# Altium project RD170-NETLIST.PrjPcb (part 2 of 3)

## Sheet 2.SchDoc
size 420 x 297 mm
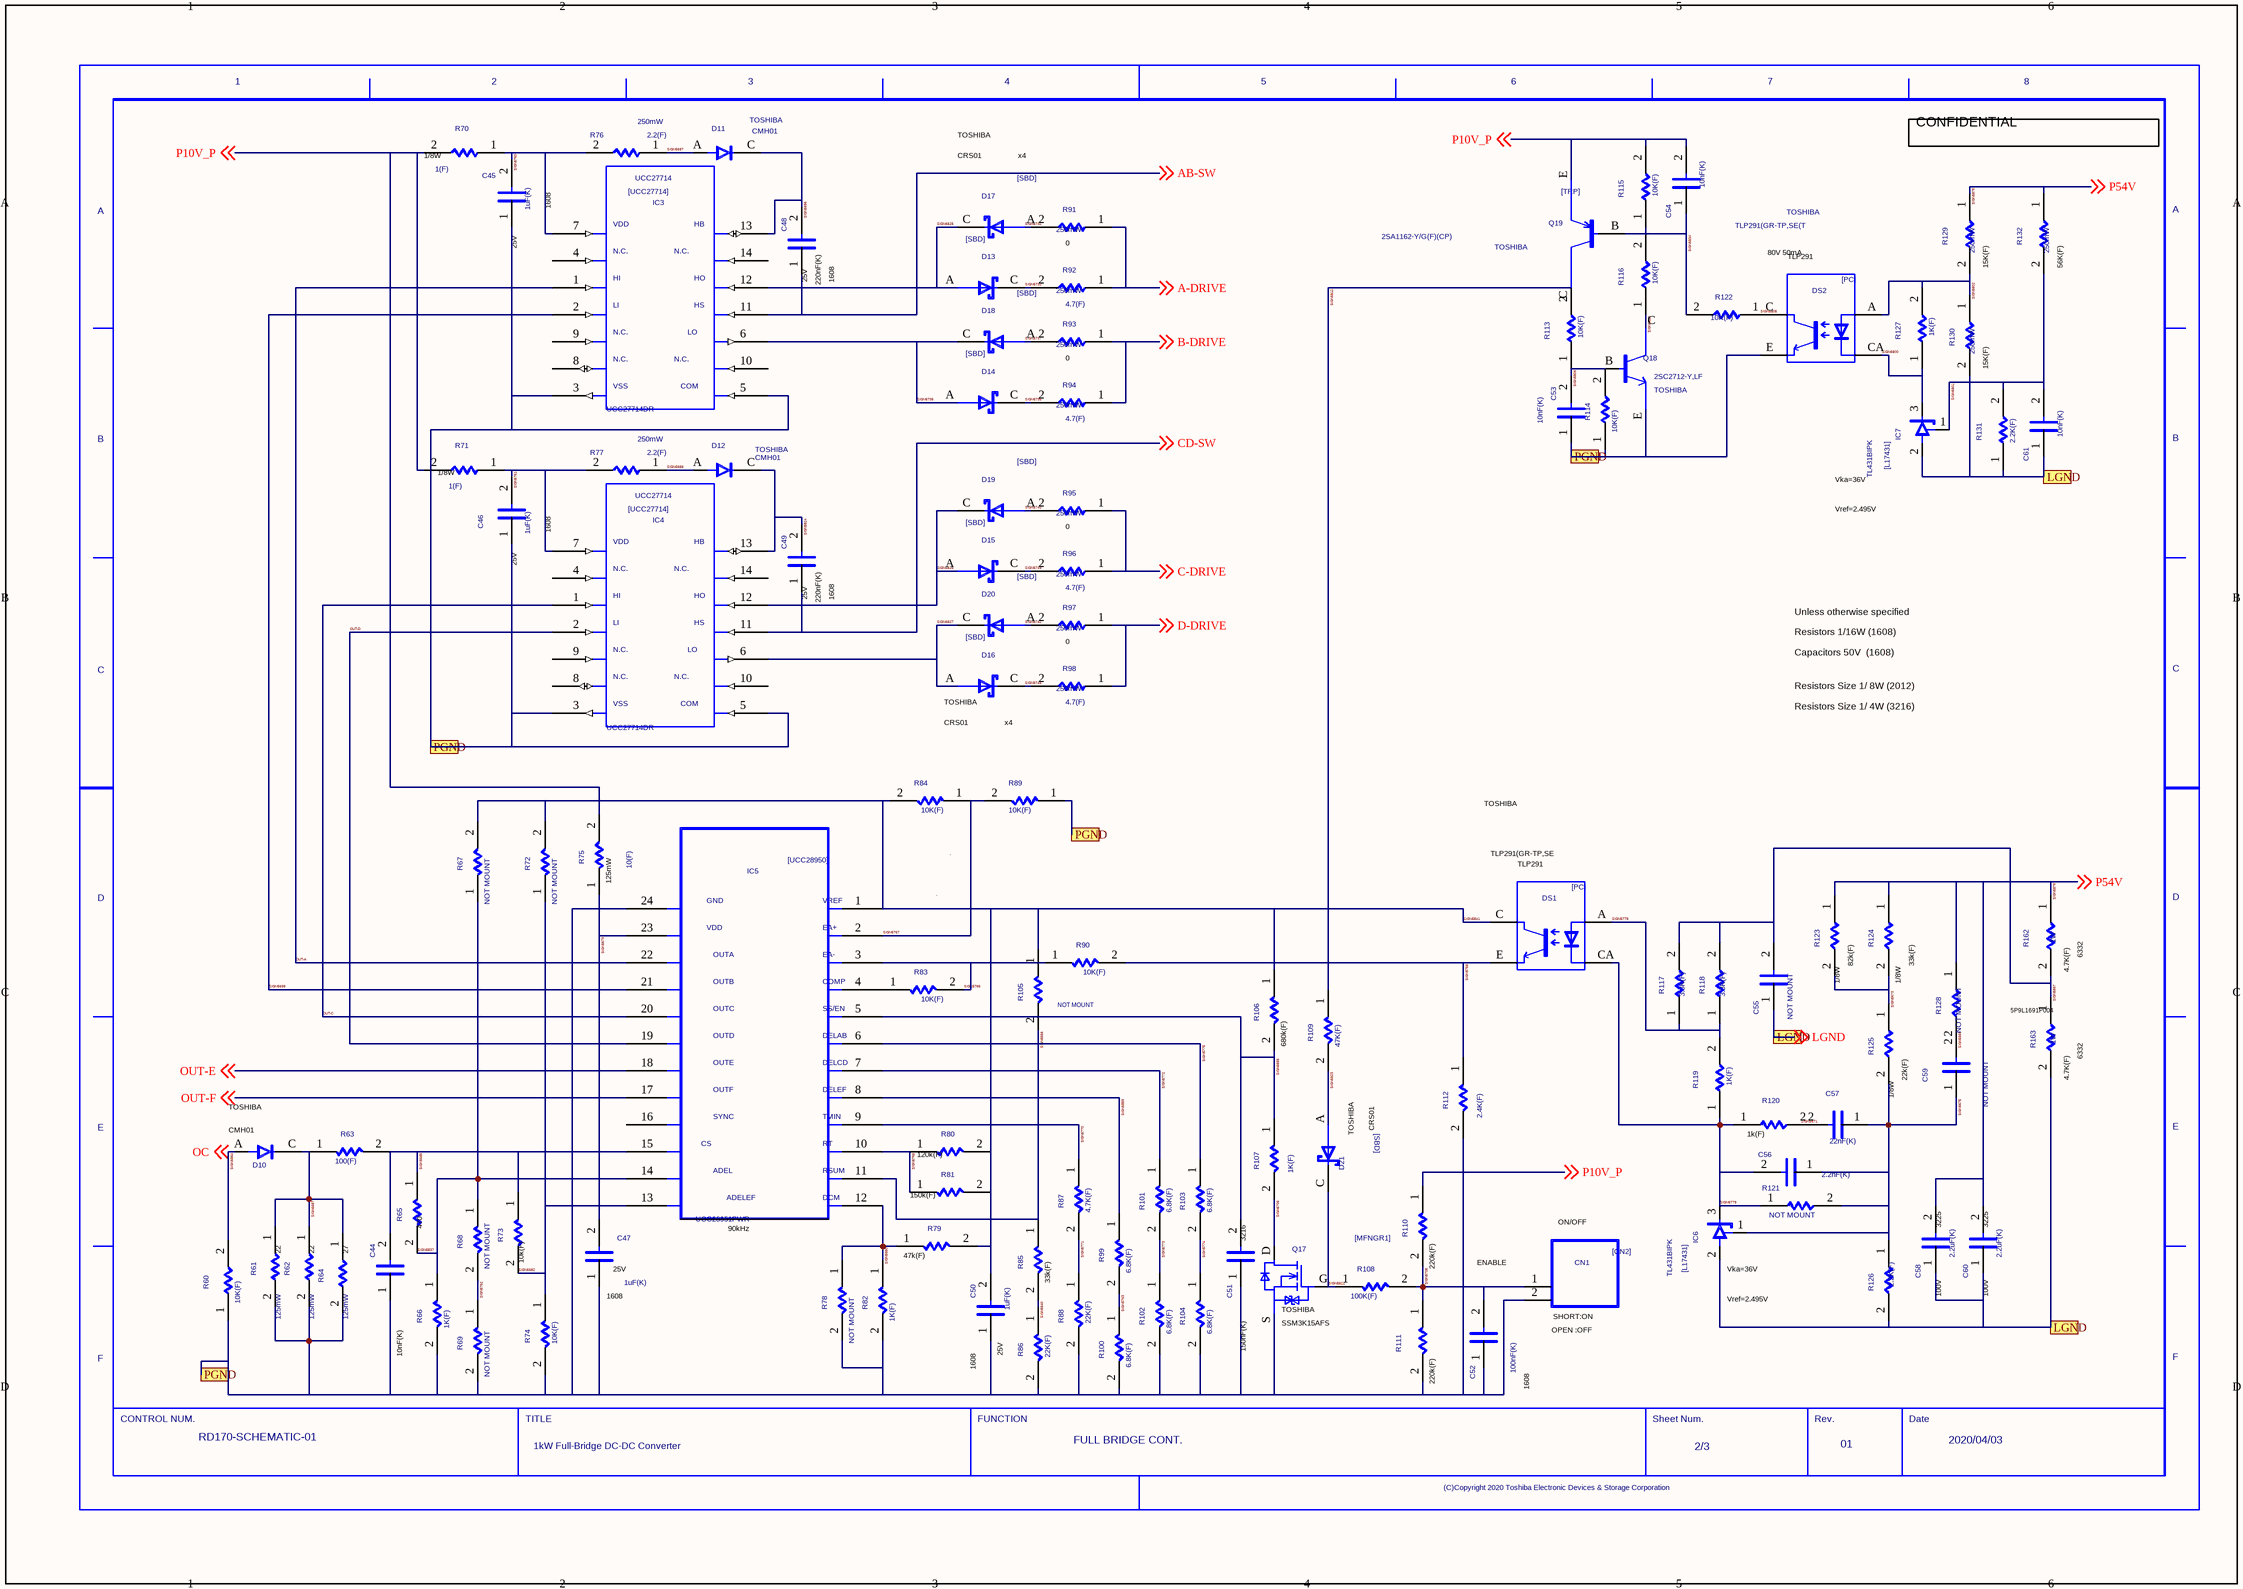
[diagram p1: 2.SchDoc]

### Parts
(Parts that share a designator on the sheet are numbered #1, #2 ... from top to bottom, then left to right.)
C44  C  (value not drawn)
C45  VAL1: 1uF(K)  (hidden comment: C)
C46  VAL1: 1uF(K)  (hidden comment: C)
C47  VAL1: 1uF(K)  (hidden comment: C)
C48  C  (value not drawn)
C49  C  (value not drawn)
C50  VAL1: 1uF(K)  (hidden comment: C)
C51  C  (value not drawn)
C52  VAL1: 100nF(K)  (hidden comment: C)
C53  VAL1: 10nF(K)  (hidden comment: C)
C54  VAL1: 10nF(K)  (hidden comment: C)
C55  NOTMOUNT: NOT MOUNT  (hidden comment: C)
C56  VAL1: 2.2nF(K)  (hidden comment: C)
C57  VAL1: 22nF(K)  (hidden comment: C)
C58  VAL1: 2.2uF(K)  (hidden comment: C)
C59  NOTMOUNT: NOT MOUNT  (hidden comment: C)
C60  VAL1: 2.2uF(K)  (hidden comment: C)
C61  VAL1: 10nF(K)  (hidden comment: C)
CN1  CN2  (value not drawn)
D10  D  (value not drawn)
D11  USERCOMPTEXT3: TOSHIBA  VAL3: CMH01  (hidden comment: D)
D12  USERCOMPTEXT3: TOSHIBA  VAL3: CMH01  (hidden comment: D)
D13  SBD  (value not drawn)
D14  SBD  (value not drawn)
D15  SBD  (value not drawn)
D16  SBD  (value not drawn)
D17  SBD  (value not drawn)
D18  SBD  (value not drawn)
D19  SBD  (value not drawn)
D20  SBD  (value not drawn)
D21  SBD  (value not drawn)
DS1  PC  (value not drawn)
DS2  USERCOMPTEXT3: TOSHIBA  VAL3: TLP291(GR-TP,SE(T  (hidden comment: PC)
IC3  VAL3: UCC27714DR  (hidden comment: UCC27714)
IC4  VAL3: UCC27714DR  (hidden comment: UCC27714)
IC5  VAL3: UCC28951PWR  (hidden comment: UCC28950)
IC6  VAL3: TL431BIPK  (hidden comment: L17431)
IC7  VAL3: TL431BIPK  (hidden comment: L17431)
Q17  MFNGR1  (value not drawn)
Q18  USERCOMPTEXT3: TOSHIBA  VAL3: 2SC2712-Y,LF  (hidden comment: TRN)
Q19  USERCOMPTEXT3: TOSHIBA  VAL3: 2SA1162-Y/G(F)(CP)  (hidden comment: TRP)
R60  VAL1: 10K(F)  (hidden comment: R)
R61  VAL2: 125mW  (hidden comment: R)
R62  VAL2: 125mW  (hidden comment: R)
R63  VAL1: 100(F)  (hidden comment: R)
R64  VAL2: 125mW  (hidden comment: R)
R65  R  (value not drawn)
R66  VAL1: 1K(F)  (hidden comment: R)
R67  NOTMOUNT: NOT MOUNT  (hidden comment: R)
R68  NOTMOUNT: NOT MOUNT  (hidden comment: R)
R69  NOTMOUNT: NOT MOUNT  (hidden comment: R)
R70  VAL1: 1(F)  (hidden comment: R)
R71  VAL1: 1(F)  (hidden comment: R)
R72  NOTMOUNT: NOT MOUNT  (hidden comment: R)
R73  R  (value not drawn)
R74  VAL1: 10K(F)  (hidden comment: R)
R75  VAL1: 10(F)  (hidden comment: R)
R76  VAL2: 250mW  VAL1: 2.2(F)  (hidden comment: R)
R77  VAL2: 250mW  VAL1: 2.2(F)  (hidden comment: R)
R78  NOTMOUNT: NOT MOUNT  (hidden comment: R)
R79  R  (value not drawn)
R80  R  (value not drawn)
R81  R  (value not drawn)
R82  VAL1: 1K(F)  (hidden comment: R)
R83  VAL1: 10K(F)  (hidden comment: R)
R84  VAL1: 10K(F)  (hidden comment: R)
R85  R  (value not drawn)
R86  VAL1: 22K(F)  (hidden comment: R)
R87  VAL1: 4.7K(F)  (hidden comment: R)
R88  VAL1: 22K(F)  (hidden comment: R)
R89  VAL1: 10K(F)  (hidden comment: R)
R90  VAL1: 10K(F)  (hidden comment: R)
R91  VAL2: 250mW  (hidden comment: R)
R92  VAL2: 250mW  VAL1: 4.7(F)  (hidden comment: R)
R93  VAL2: 250mW  (hidden comment: R)
R94  VAL2: 250mW  VAL1: 4.7(F)  (hidden comment: R)
R95  VAL2: 250mW  (hidden comment: R)
R96  VAL2: 250mW  VAL1: 4.7(F)  (hidden comment: R)
R97  VAL2: 250mW  (hidden comment: R)
R98  VAL2: 250mW  VAL1: 4.7(F)  (hidden comment: R)
R99  VAL1: 6.8K(F)  (hidden comment: R)
R100  VAL1: 6.8K(F)  (hidden comment: R)
R101  VAL1: 6.8K(F)  (hidden comment: R)
R102  VAL1: 6.8K(F)  (hidden comment: R)
R103  VAL1: 6.8K(F)  (hidden comment: R)
R104  VAL1: 6.8K(F)  (hidden comment: R)
R105  NOTMOUNT: NOT MOUNT  (hidden comment: R)
R106  R  (value not drawn)
R107  VAL1: 1K(F)  (hidden comment: R)
R108  VAL1: 100K(F)  (hidden comment: R)
R109  VAL1: 47K(F)  (hidden comment: R)
R110  R  (value not drawn)
R111  R  (value not drawn)
R112  VAL1: 2.4K(F)  (hidden comment: R)
R113  VAL1: 10K(F)  (hidden comment: R)
R114  VAL1: 10K(F)  (hidden comment: R)
R115  VAL1: 10K(F)  (hidden comment: R)
R116  VAL1: 10K(F)  (hidden comment: R)
R117  VAL1: 3.3K(F)  (hidden comment: R)
R118  VAL1: 3.3K(F)  (hidden comment: R)
R119  VAL1: 1K(F)  (hidden comment: R)
R120  R  (value not drawn)
R121  NOTMOUNT: NOT MOUNT  (hidden comment: R)
R122  VAL1: 10K(F)  (hidden comment: R)
R123  R  (value not drawn)
R124  R  (value not drawn)
R125  R  (value not drawn)
R126  VAL1: 2.2K(F)  (hidden comment: R)
R127  VAL1: 1K(F)  (hidden comment: R)
R128  NOTMOUNT: NOT MOUNT  (hidden comment: R)
R129  VAL2: 250mW  (hidden comment: R)
R130  VAL2: 250mW  (hidden comment: R)
R131  VAL1: 2.2K(F)  (hidden comment: R)
R132  VAL2: 250mW  (hidden comment: R)
R162  VAL2: 1W  (hidden comment: R)
R163  VAL2: 1W  (hidden comment: R)
U?#2  DATE: 2020/04/03  REVISION: 01  SHEETNUMBER: 2/3  FUNCTION: FULL BRIDGE CONT.  DRAWINGNUMBER: RD170-SCHEMATIC-01  TITLE: 1kW Full-Bridge DC-DC Converter  (hidden comment: WAKU_DEF100)

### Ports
LGND, PGND

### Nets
A-DRIVE: R91.1 R92.1 ; off-sheet A-DRIVE
AB-SW: C48.1 IC3.11 ; off-sheet AB-SW
B-DRIVE: R93.1 R94.1 ; off-sheet B-DRIVE
C-DRIVE: R95.1 R96.1 ; off-sheet C-DRIVE
CD-SW: C49.1 IC4.11 ; off-sheet CD-SW
D-DRIVE: R97.1 R98.1 ; off-sheet D-DRIVE
OUT-A: IC3.1 IC5.22
OUT-C: IC4.1 IC5.20
OUT-D: IC4.2 IC5.19
OUT-E: IC5.18 ; off-sheet OUT-E
OUT-F: IC5.17 ; off-sheet OUT-F
P10V_P: C54.2 Q19.E R70.2 R71.2 R75.2 R110.1 R115.2 ; off-sheet P10V_P
PGND: C44.1 C45.1 C46.1 C47.1 C50.1 C51.1 C52.1 C53.1 CN1.2 DS2.E IC3.3 IC3.5 IC4.3 IC4.5 IC5.24 Q17.S Q18.E R60.1 R61.2 R62.2 R64.2 R66.2 R69.2 R74.2 R78.2 R82.2 R86.2 R88.2 R89.1 R100.2 R102.2 R104.2 R111.2 R112.2 R114.1 ; port PGND
SIGN5566: IC5.11 R85.1 R105.2
SIGN5650: IC5.12 R78.1 R79.1 R82.1
SIGN5655: C51.2 IC5.5 R106.2 R107.1
SIGN5668: C59.2 R128.2
SIGN5671: C57.2 R120.2
SIGN5673: R123.2 R124.2 R125.1
SIGN5675: C56.1 C57.1 C59.1 IC6.1 R121.2 R125.2 R126.1
SIGN5679: C47.2 IC5.23 R75.1
SIGN5682: IC5.13 R72.1 R73.2 R74.1
SIGN5685: C44.2 IC5.15 R63.2 R65.1 R73.1
SIGN5687: D10.C R61.1 R62.1 R63.1 R64.1
SIGN5688: D12.A R77.1
SIGN5696: C48.2 D11.C IC3.13
SIGN5697: D11.A R76.1
SIGN5699: IC3.2 IC5.21
SIGN5705: Q17.D R107.2
SIGN5708: C52.2 CN1.1 R108.2 R110.2 R111.1
SIGN5732: D17.A R91.2
SIGN5733: D13.C R92.2
SIGN5735: D14.A D18.C IC3.6
SIGN5736: D14.C R94.2
SIGN5737: D18.A R93.2
SIGN5739: D15.C R96.2
SIGN5740: D19.A R95.2
SIGN5742: D20.A R97.2
SIGN5744: D16.C R98.2
SIGN5758: DS1.E R90.2 R112.1
SIGN5760: C45.2 IC3.7 R70.1 R76.2
SIGN5761: C46.2 IC4.7 R71.1 R77.2
SIGN5762: R68.2 R69.1
SIGN5763: R99.2 R100.1
SIGN5766: IC5.3 R83.2 R90.1
SIGN5767: IC5.2 R84.1 R89.2
SIGN5768: IC5.10 R80.1 R81.1
SIGN5770: IC5.9 R87.1
SIGN5771: R87.2 R88.1
SIGN5772: IC5.7 R101.1
SIGN5773: R101.2 R102.1
SIGN5774: R103.2 R104.1
SIGN5775: IC5.6 R103.1
SIGN5778: DS1.A R117.1 R118.1 R119.2
SIGN5779: C56.2 DS1.CA IC6.3 R119.1 R120.1 R121.1
SIGN5800: DS2.CA IC7.3 R127.1
SIGN5801: C61.2 IC7.1 R131.2 R132.2
SIGN5802: DS2.A R127.2 R129.2 R130.1
SIGN5805: DS2.C R122.1
SIGN5806: C53.2 Q18.B R113.1 R114.2
SIGN5812: Q19.C R109.1 R113.2
SIGN5822: D21.C Q17.G R108.1
SIGN5823: D21.A R109.2
SIGN5824: C49.2 D12.C IC4.13
SIGN5825: D13.A D17.C IC3.12
SIGN5826: D15.A D19.C IC4.12
SIGN5827: D16.A D20.C IC4.6
SIGN5828: Q18.C R116.1
SIGN5834: C54.1 Q19.B R115.1 R116.2 R122.2
SIGN5837: IC5.14 R65.2 R66.1 R67.1 R68.1
SIGN5840: R85.2 R86.1
SIGN5841: C50.2 DS1.C IC5.1 R67.2 R72.2 R79.2 R80.2 R81.2 R84.2 R105.1 R106.1
SIGN5859: IC5.8 R99.1
SIGN5864: D10.A R60.2 ; off-sheet OC  [also labelled OC]
SIGN5867: C55.2 R117.2 R118.2 R162.2 R163.1
SIGN5873: C55.1 C58.1 C60.1 C61.1 IC6.2 IC7.2 R126.2 R130.2 R131.1 R163.2 ; off-sheet LGND, port LGND  [also labelled LGND]
SIGN5875: C58.2 C60.2 R123.1 R124.1 R128.1 R129.1 R132.1 R162.1 ; off-sheet P54V  [also labelled P54V]
NetIC5_4: IC5.4 R83.1

Not connected (* = marked no-connect by the designer): IC3 4 8 9 10 14; IC4 4 8 9 10 14; IC5 16

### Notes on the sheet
- CONFIDENTIAL
- (near R70) 1/8W
- CRS01
- TOSHIBA
- x4
- (near C45) 25V
- 1608
- (near R91) 0
- 80V 50mA
  CTR=100-300
- TLP291
- (near C48) 25V
- (near C48) 220nF(K)
- (near C48) 1608
- (near R129) 15K(F)
- (near R132) 56K(F)
- (near R93) 0
- (near R130) 15K(F)
- (near R71) 1/8W
- (near R95) 0
- Vref=2.495V
  +-0.5%
- Vka=36V
- (near C46) 25V
- (near C49) 25V
- (near C49) 220nF(K)
- (near C49) 1608
- (near R97) 0
- Unless otherwise specified
- Resistors 1/16W (1608)
- Capacitors 50V  (1608)
- (near D16) CRS01
- (near D16) TOSHIBA
- (near D16) x4
- Resistors Size 1/ 8W (2012)
- Resistors Size 1/ 4W (3216)
- TLP291(GR-TP,SE
  80V 50mA
  CTR=100-300
- (near DS1) TLP291
- (near R75) 125mW
- (near R123) 1/8W
- (near R123) 82k(F)
- (near R124) 1/8W
- (near R124) 33k(F)
- (near R162) 4.7K(F)
- (near R162) 6332
- (near R106) 680k(F)
- (near R163) 5P9L1691P004
- (near R163) 6332
- (near D10) CMH01
  200V3A
- (near D10) TOSHIBA
- (near D21) TOSHIBA
- (near D21) CRS01
- (near R120) 1k(F)
- (near R125) 1/8W
- (near R125) 22k(F)
- (near R163) 4.7K(F)
- (near R81) 150k(F)
- (near R80) 120k(F)
- (near R61) 22
- (near R62) 22
- (near R64) 27
- (near R65) 470
- (near R73) 10k(F)
- (near C47) 25V
- (near IC5) 90kHz
- (near R79) 47k(F)
- (near C51) 3216
- (near R110) 220k(F)
- ENABLE
- ON/OFF
- (near IC6) Vka=36V
- (near C58) 3225
- (near C60) 3225
- (near C47) 1608
- (near R85) 33k(F)
- (near Q17) SSM3K15AFS
- (near Q17) TOSHIBA
- (near CN1) OPEN :OFF
- (near CN1) SHORT:ON
- 100V
- (near C60) 100V
- (near R66) 10nF(K)
- 25V
- 150nF(K)
- (near R111) 220k(F)

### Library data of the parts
C44 = C: SQ_PART_MODEL: CON_10n; FNPARTSNAMEG: CHIP CERAMIC CAPACITOR (1608); USEINPARTSLIST: YES; PARTNAME: G36030011044; OriginalSymbolOrigin: (2540,7620); MFSOLDERINGPROP: .; TEMPCHARACTERI2: B; MFPACKAGEMETHOP: S; MFFORMINGDIVP: KC; OUMECLASSIFICATION: セラミックコンデンサ; SIZECODESMD: 1608; MFMOUNTSYMBOLP: 80; CDMASTERCADCELG: C8100E; PCODE: P03039045226; FNCLASSCODEG: P03-03; TOLERANCE: K; RATEDVOLTAGE: 50; COMPONENTNAME: G36030011044_package; MAXGCOUNT: 1; OUMEMAKER: MRT 村田製作所; NOMINALCAPACITA: 1n; OUMEMAKERKATAMEI: GRM39B102K50PT; VAL2: 50V; VAL1: 10nF(K)
C45 = C: SQ_PART_MODEL: CON_1u; FNPARTSNAMEG: CHIP CERAMIC CAPACITOR (1608); USEINPARTSLIST: YES; PARTNAME: G36030011846; OriginalSymbolOrigin: (2540,7620); PCODE: P03B0000000N; MFSOLDERINGPROP: .; TEMPCHARACTERI2: B; MFPACKAGEMETHOP: S; MFFORMINGDIVP: KC; OUMECLASSIFICATION: セラミックコンデンサ; SIZECODESMD: 1608; MFMOUNTSYMBOLP: 80; CDMASTERCADCELG: C8100E; FNCLASSCODEG: P03-03; RATEDVOLTAGE: 6.3; COMPONENTNAME: G36030011846_package; MAXGCOUNT: 1; OUMEMAKER: MRT 村田製作所; NOMINALCAPACITA: 1u; OUMEMAKERKATAMEI: GRM39B105K6.3PC; VAL2: 25V; CAPACITANCETOLE: K
C46 C47 C50 = C: SQ_PART_MODEL: CON_1u; FNPARTSNAMEG: CHIP CERAMIC CAPACITOR (1608); USEINPARTSLIST: YES; PARTNAME: G36030011846; OriginalSymbolOrigin: (2540,7620); MFSOLDERINGPROP: .; TEMPCHARACTERI2: B; MFPACKAGEMETHOP: S; MFFORMINGDIVP: KC; OUMECLASSIFICATION: セラミックコンデンサ; SIZECODESMD: 1608; MFMOUNTSYMBOLP: 80; CDMASTERCADCELG: C8100E; PCODE: P03B0000000N; FNCLASSCODEG: P03-03; RATEDVOLTAGE: 6.3; COMPONENTNAME: G36030011846_package; MAXGCOUNT: 1; OUMEMAKER: MRT 村田製作所; NOMINALCAPACITA: 1u; OUMEMAKERKATAMEI: GRM39B105K6.3PC; VAL2: 25V; CAPACITANCETOLE: K
C48 C49 = C: SQ_PART_MODEL: CON_220n; FNPARTSNAMEG: CHIP CERAMIC CAPACITOR (3216); USEINPARTSLIST: YES; PARTNAME: GDM030000714; OriginalSymbolOrigin: (2540,7620); MFSOLDERINGPROP: .; TEMPCHARACTERI2: B; MFFORMINGDIVP: KC; OUMECLASSIFICATION: セラミックコンデンサ; SIZECODESMD: 3216; MFMOUNTSYMBOLP: 90; CDMASTERCADCELG: DC901A; PCODE: P03042A01127; FNCLASSCODEG: P03-03; MFPACKAGEMETHOP: S; TOLERANCE: K; RATEDVOLTAGE: 100; COMPONENTNAME: 5P9L1192P002_package; MAXGCOUNT: 1; OUMEMAKER: 株式会社村田製作所; NOMINALCAPACITA: 47n; OUMEMAKERKATAMEI: GRM31MR72A473KA01L; VAL2: 25V; VAL1: 220nF(K)
C51 = C: SQ_PART_MODEL: CON_150n; FNPARTSNAMEG: CHIP CERAMIC CAPACITOR (3216); USEINPARTSLIST: YES; PARTNAME: 5P9L1192P002; OriginalSymbolOrigin: (2540,7620); MFSOLDERINGPROP: .; TEMPCHARACTERI2: B; MFFORMINGDIVP: KC; OUMECLASSIFICATION: セラミックコンデンサ; SIZECODESMD: 3216; MFMOUNTSYMBOLP: 90; CDMASTERCADCELG: DC901A; PCODE: P03042A01127; FNCLASSCODEG: P03-03; TOLERANCE: K; RATEDVOLTAGE: 100; COMPONENTNAME: 5P9L1192P002_package; MAXGCOUNT: 1; OUMEMAKER: 株式会社村田製作所; MFPACKAGEMETHOP: S; NOMINALCAPACITA: 47n; OUMEMAKERKATAMEI: GRM31MR72A473KA01L; VAL3: 8.85E+11; VAL2: 100V; VAL1: 150nF(K)
C52 = C: SQ_PART_MODEL: CON_100n; FNPARTSNAMEG: CHIP CERAMIC CAPACITOR (1608); USEINPARTSLIST: YES; PARTNAME: G36030104036; OriginalSymbolOrigin: (2540,7620); MFSOLDERINGPROP: .; TEMPCHARACTERI2: B; MFFORMINGDIVP: KC; OUMECLASSIFICATION: セラミックコンデンサ; SIZECODESMD: 1608; MFMOUNTSYMBOLP: 80; CDMASTERCADCELG: C8100E; PCODE: P03039A6F224; FNCLASSCODEG: P03-03; RATEDVOLTAGE: 25; COMPONENTNAME: G36030104036_package; MAXGCOUNT: 1; OUMEMAKER: MRT 村田製作所; MFPACKAGEMETHOP: S; NOMINALCAPACITA: 100n; OUMEMAKERKATAMEI: GRM39B104K25PT; VAL2: 50V; CAPACITANCETOLE: K
C53 C54 C61 = C: SQ_PART_MODEL: CON_10n; FNPARTSNAMEG: CHIP CERAMIC CAPACITOR (1608); USEINPARTSLIST: YES; PARTNAME: GDM030000538; OriginalSymbolOrigin: (2540,7620); MFSOLDERINGPROP: .; TEMPCHARACTERI2: B; MFPACKAGEMETHOP: S; MFFORMINGDIVP: KC; FNLEADFREETHET1GT2GMCTH1: 3_1_N; OUMECLASSIFICATION: セラミックコンデンサ; SIZECODESMD: 1608; MFMOUNTSYMBOLP: 80; CDMASTERCADCELG: C8100E; PCODE: P03039A11122; FNCLASSCODEG: P03-03; NOTMOUNT: MOUNT; RATEDVOLTAGE: 50; COMPONENTNAME: GDM030000538_package; MAXGCOUNT: 1; OUMEMAKER: KYC 京セラ; NOMINALCAPACITA: 10n; OUMEMAKERKATAMEI: CM105W5R103K50AT; VAL2: 50V; CAPACITANCETOLE: K
C55 = C: FNPARTSNAMEG: CHIP CERAMIC CAPACITOR (3216); USEINPARTSLIST: YES; PARTNAME: G36030104036; OriginalSymbolOrigin: (2540,7620); MFSOLDERINGPROP: .; MFMOUNTSYMBOLP: 90; TOLERANCE: K; FNLEADFREETHET1GT2GMCTH1: 3_1_N; RATEDVOLTAGE: 50; COMPONENTNAME: G36030031295_package; MAXGCOUNT: 1; TEMPCHARACTERI2: B; OUMEMAKER: TYD 太陽誘電; MFPACKAGEMETHOP: S; MFFORMINGDIVP: KC; OUMECLASSIFICATION: セラミックコンデンサ; SIZECODESMD: 3216; FUNCTION: G36030031295; NOMINALCAPACITA: 100n; OUMEMAKERKATAMEI: UMK316BJ104KD-T; CDMASTERCADCELG: DC901A; PCODE: P03042943816; FNCLASSCODEG: P03-03
C56 = C: SQ_PART_MODEL: CON_2.2n; FNPARTSNAMEG: CHIP CERAMIC CAPACITOR (1608); USEINPARTSLIST: YES; PARTNAME: GDM030000558; OriginalSymbolOrigin: (2540,7620); PCODE: P03039A0H125; NOTMOUNT: MOUNT; MFSOLDERINGPROP: .; MFMOUNTSYMBOLP: 80; RATEDVOLTAGE: 50; TEMPCHARACTERI2: B; MFPACKAGEMETHOP: S; MFFORMINGDIVP: KC; FNLEADFREETHET1GT2GMCTH1: 3_1_N; OUMECLASSIFICATION: セラミックコンデンサ; SIZECODESMD: 1608; NOMINALCAPACITA: 2.2n; CAPACITANCETOLE: K; CDMASTERCADCELG: C8100E; FNCLASSCODEG: P03-03; VAL2: 50V; COMPONENTNAME: GDM030000558_package; MAXGCOUNT: 1; OUMEMAKER: KYC 京セラ; OUMEMAKERKATAMEI: CM105W5R222K50AT
C57 = C: SQ_PART_MODEL: CON_22n; FNPARTSNAMEG: CHIP CERAMIC CAPACITOR (1608); PARTCOMMENT: 代表セル<KC0008> がフットプリントに登録されていません。; USEINPARTSLIST: YES; PARTNAME: GDM030000558; OriginalSymbolOrigin: (2540,7620); NOTMOUNT: MOUNT; MFSOLDERINGPROP: .; MFMOUNTSYMBOLP: 80; RATEDVOLTAGE: 50; TEMPCHARACTERI2: B; MFPACKAGEMETHOP: S; MFFORMINGDIVP: KC; FNLEADFREETHET1GT2GMCTH1: 3_1_N; OUMECLASSIFICATION: セラミックコンデンサ; SIZECODESMD: 1608; NOMINALCAPACITA: 22n; CAPACITANCETOLE: K; CDMASTERCADCELG: KC0008; FNCLASSCODEG: P03-03; VAL2: 50V; COMPONENTNAME: K0300277_package; MAXGCOUNT: 1; OUMEMAKER: ROH ロー・; OUMEMAKERKATAMEI: MCH185CN223KK
C58 C60 = C: SQ_PART_MODEL: CON_1u; FNPARTSNAMEG: CHIP CERAMIC CAPACITOR (3216); USEINPARTSLIST: YES; PARTNAME: G36030013017; OriginalSymbolOrigin: (2540,7620); MFSOLDERINGPROP: .; TEMPCHARACTERI2: B; MFPACKAGEMETHOP: S; MFFORMINGDIVP: KC; FNLEADFREETHET1GT2GMCTH1: 3_1_N; OUMECLASSIFICATION: セラミックコンデンサ; SIZECODESMD: 3216; MFMOUNTSYMBOLP: 90; CDMASTERCADCELG: DC901A; PCODE: P03042992821; FNCLASSCODEG: P03-03; TOLERANCE: K; NOTMOUNT: MOUNT; RATEDVOLTAGE: 50; COMPONENTNAME: 5P9L1192P006_package; MAXGCOUNT: 1; OUMEMAKER: 株式会社村田製作所; NOMINALCAPACITA: 1u; OUMEMAKERKATAMEI: GRM31MB31H105KA87L; VAL3: 8.85E+11; VAL2: 100V
C59 = C: FNPARTSNAMEG: CHIP CERAMIC CAPACITOR (3216); USEINPARTSLIST: YES; PARTNAME: G36030031271; OriginalSymbolOrigin: (2540,7620); MFSOLDERINGPROP: .; MFMOUNTSYMBOLP: 90; FNLEADFREETHET1GT2GMCTH1: 3_1_N; RATEDVOLTAGE: 100; COMPONENTNAME: G36030031271_package; MAXGCOUNT: 1; TEMPCHARACTERI2: F; OUMEMAKER: KYC 京セラ; MFPACKAGEMETHOP: S; MFFORMINGDIVP: KC; OUMECLASSIFICATION: セラミックコンデンサ; SIZECODESMD: 3216; NOMINALCAPACITA: 100n; OUMEMAKERKATAMEI: CM316Y5V104Z100AT; CAPACITANCETOLE: Z; CDMASTERCADCELG: DC901A; PCODE: P03042366127; FNCLASSCODEG: P03-03
CN1 = CN2: USEINPARTSLIST: YES; PARTNAME: ZS_DPJ028; OUMEPARTTYPE: PJ; OriginalSymbolOrigin: (2540,15240); VAL3: PSS-410253-02; MAXGCOUNT: 1; COMPONENTNAME: ZS_DPJ028_package; QUADMODEL: dummymodel
D10 = D: USEINPARTSLIST: YES; PARTNAME: 5P9L1110P002; SAVEAREA0: -565,-171,12979,8058; SAVECOUNT: 1; OriginalSymbolOrigin: (2540,5080); COMPONENTNAME: D_D; OUMEMAKER: 東芝; OUMEMAKERKATAMEI: CMF02(TE12R,Q); VAL3: CMH01(TE12L,Q)
D11 D12 = D: USEINPARTSLIST: YES; PARTNAME: 5P9L1110P002; SAVEAREA0: -565,-171,12979,8058; SAVECOUNT: 1; OriginalSymbolOrigin: (2540,5080); COMPONENTNAME: D_D; OUMEMAKER: 東芝; OUMEMAKERKATAMEI: CMF02(TE12R,Q); VAL1: CMH01(TE12L,Q)
D13-D21 = SBD: FNPARTSNAMEG: SCHOTTKY BARRIER DIODE; USEINPARTSLIST: YES; PARTNAME: G36420146011; OUMEPARTTYPE: D; OriginalSymbolOrigin: (0,5080); FORWARDVOLTAGEM: 0; COMPONENTNAME: G36420146011_package; MAXGCOUNT: 1; MAXREPETITIVEPE: 30; MFSOLDERINGPROP: .; OUMEMAKER: TSB 東芝（ＹＰＳＳ）; QUADMODEL: dummymodel; MFPACKAGEMETHOP: S; PEAKFORWARDVOLT: 360m; MFFORMINGDIVP: MM; MOUNTINGFORMSMD: SMD; OUMECLASSIFICATION: 一般整流素子; MFMOUNTSYMBOLP: 80; OUMEMAKERKATAMEI: CRS01(TE85L); VAL3: CRS01(TE85L,Q); CDMASTERCADCELG: DD831R; PCODE: P42471001117; FNCLASSCODEG: P42-03
DS1 = PC: USEINPARTSLIST: YES; PARTNAME: TLP291_GR-TP_SE; OriginalSymbolOrigin: (5080,17780); VAL3: TLP291(GR-TP,SE(T; MAXGCOUNT: 1; COMPONENTNAME: pinass:PC_func:PC; OUMEMAKER: 東芝; OUMEMAKERKATAMEI: TLP291(GR-TP,SE
DS2 = PC: USEINPARTSLIST: YES; PARTNAME: TLP291_GR-TP_SE; OriginalSymbolOrigin: (5080,17780); MAXGCOUNT: 1; COMPONENTNAME: pinass:PC_func:PC; OUMEMAKER: 東芝; OUMEMAKERKATAMEI: TLP291(GR-TP,SE
IC3 IC4 = UCC27714: PARTS: 1; SAVECOUNT: 17; SAVEAREA0: -9583,0,50301,45720; TIME: 14:04:55; UPDATEUSER: q91866sr; UPDATETIME: 15:13:25; DEVICENAME: 74HC244AF; DEVICE: 74VHC245; PKG_TYPE: 20PIN; LEVEL: STD; HETERO: 74VHC245,74VHC245_P; OriginalSymbolOrigin: (7620,45720); FUNCTION: IRS21864S
IC5 = UCC28950: USEINPARTSLIST: YES; SAVECOUNT: 69; SAVEAREA0: -101871,-17388,148743,93366; TIME: 18:25:15; UPDATEUSER: S.Itagaki; UPDATETIME: 11:59:25; OriginalSymbolOrigin: (7620,76200); MAXGCOUNT: 1; COMPONENTNAME: UCC28950_UCC28950; OUMEMAKER: Texas Instruments; OUMEMAKERKATAMEI: UCC28950PWR
IC6 IC7 = L17431: FNPARTSNAMEG: SHUNT REGULATOR; USEINPARTSLIST: YES; PARTNAME: 5P9L1152P001; OUMEPARTTYPE: IC; OriginalSymbolOrigin: (2540,7620); COMPONENTNAME: 5P9L1152P001_package; MAXGCOUNT: 1; MFSOLDERINGPROP: .; OUMEMAKER: ルネサステクノロジー; QUADMODEL: dummymodel; MFPACKAGEMETHOP: S; MFFORMINGDIVP: MM; MOUNTINGFORMSMD: SMD; FNLEADFREETHET1GT2GMCTH1: N_0_N; OUMECLASSIFICATION: レギュレータ; MFMOUNTSYMBOLP: 90; OUMEMAKERKATAMEI: HA17431UA-TL-E; CDMASTERCADCELG: DI9821; KIND: VRGL; PCODE: P47186011147; FNCLASSCODEG: P47-04
Q17 = MFNGR1: FNPARTSNAMEG: N-CH MOS FET; USEINPARTSLIST: YES; PARTNAME: GDM410000111; OUMEPARTTYPE: Q; SAVECOUNT: 24; SAVEAREA0: -14204,-8572,26849,21288; TIME: 16:49:03; UPDATEUSER: ikeda-k; UPDATETIME: 18:49:38; OriginalSymbolOrigin: (2540,10160); MAXGCOUNT: 1; COMPONENTNAME: GDM410000111_package; MFSOLDERINGPROP: .; OUMEMAKER: TSB 東芝（ＹＰＳＳ）; QUADMODEL: dummymodel; MFPACKAGEMETHOP: S; MFFORMINGDIVP: MM; MOUNTINGFORMSMD: SMD; OUMECLASSIFICATION: MOS-FET; MFMOUNTSYMBOLP: 80; MAXGDVOLTAGE: 0; MAXDRAINCURRENT: 100m; OUMEMAKERKATAMEI: SSM3K15FS(TE85L); MAXGSVOLTAGE: 20; VAL3: SSM3K15AFS,LF; CDMASTERCADCELG: DQ815R; PCODE: P41B0000007E; MAXDSVOLTAGE: 30; FNCLASSCODEG: P41-05
Q18 = TRN: FNPARTSNAMEG: NPN TRANSISTOR; USEINPARTSLIST: YES; PARTNAME: 5P9L1051P002; OUMEPARTTYPE: Q; OriginalSymbolOrigin: (2540,17780); MAXGCOUNT: 1; COMPONENTNAME: 5P9L1051P002_package; MFSOLDERINGPROP: .; OUMEMAKER: 東芝セミコンダクター社; QUADMODEL: dummymodel; MFPACKAGEMETHOP: S; MFFORMINGDIVP: MM; MOUNTINGFORMSMD: SMD; OUMECLASSIFICATION: バイポーラトランジスタ; MFMOUNTSYMBOLP: 80; MAXGDVOLTAGE: 0; OUMEMAKERKATAMEI: 2SC2712-Y(TE85R,F); CDMASTERCADCELG: DQ900A; PCODE: P41117004130; MAXCOLLECTORCUR: 150m; FNCLASSCODEG: P41-01
Q19 = TRP: FNPARTSNAMEG: PNP TRANSISTOR; USEINPARTSLIST: YES; PARTNAME: 5P9L1051P004; OUMEPARTTYPE: Q; OriginalSymbolOrigin: (5080,22860); MAXGCOUNT: 1; COMPONENTNAME: 5P9L1051P004_package; MFSOLDERINGPROP: .; OUMEMAKER: 東芝セミコンダクター社; QUADMODEL: dummymodel; MFPACKAGEMETHOP: S; MFFORMINGDIVP: MM; MOUNTINGFORMSMD: SMD; OUMECLASSIFICATION: ＰＮＰバイポーラトランジスタ; MFMOUNTSYMBOLP: 90; MAXGDVOLTAGE: 0; OUMEMAKERKATAMEI: 2SA1162-Y(TE85R,F); CDMASTERCADCELG: DQ900A; PCODE: P41050002132; MAXCOLLECTORCUR: -150; FNCLASSCODEG: P41-02
R60 = R: SQ_PART_MODEL: RES_10K; FNPARTSNAMEG: CHIP RESISTOR (1608); USEINPARTSLIST: YES; PARTNAME: G5101119W105; OriginalSymbolOrigin: (5080,5080); MFSOLDERINGPROP: .; MFPACKAGEMETHOP: S; MFFORMINGDIVP: KC; MOUNTINGFORMSMD: SMD; OUMECLASSIFICATION: 表面実装用固定抵抗器; MFMOUNTSYMBOLP: 80; NUMBEROFELEMENT: 0; CDMASTERCADCELG: DR802R; PCODE: P01042049729; FNCLASSCODEG: P01-08; RESISTANCETOLER: F; POWERRATING: 63m; NOMINALRESISTAN: 10K; MAXGCOUNT: 1; OUMEPOWER: 1/4; COMPONENTNAME: G5101119W105_package; OUMEMAKER: ROH ロー・; OUMERESISTANCE: 30; OUMECHIPSIZE: 3225; OUMECELLMEI: DR903A; OUMEMAKERKATAMEI: MCR03EZPFX1002; VAL2: 63mW; PA_PHASE: SCH; PA_LOCK: LOCKED; OUMERANKU: L
R61 R62 = R#1: SQ_PART_MODEL: RES_22; FNPARTSNAMEG: CHIP RESISTOR (2012); USEINPARTSLIST: YES; PARTNAME: GDM010000073; PARTCOMMENT: 代表セル<KC0006> がフットプリントに登録されていません。; OriginalSymbolOrigin: (5080,5080); CaptureCellPackProp: R##1; MFSOLDERINGPROP: .; MFPACKAGEMETHOP: S; MFFORMINGDIVP: KC; MOUNTINGFORMSMD: SMD; OUMECLASSIFICATION: 表面実装用固定抵抗器; MFMOUNTSYMBOLP: 80; NUMBEROFELEMENT: 0; CDMASTERCADCELG: KC0006; PCODE: P01B000000XB; FNCLASSCODEG: P01-08; RESISTANCETOLER: F; POWERRATING: 125m; NOMINALRESISTAN: 6.8; MAXGCOUNT: 1; OUMEPOWER: 1/4; COMPONENTNAME: GDM010000073_package; OUMEMAKER: NAE 松下電子部品; OUMERESISTANCE: 30; OUMECHIPSIZE: 3225; OUMECELLMEI: DR903A; OUMEMAKERKATAMEI: ERJ6RQF6R8V; VAL1: 22(F); PA_PHASE: SCH; PA_LOCK: LOCKED; OUMERANKU: L
R63 = R: SQ_PART_MODEL: RES_100; FNPARTSNAMEG: CHIP RESISTOR (1608); USEINPARTSLIST: YES; PARTNAME: G36010104087; OriginalSymbolOrigin: (5080,5080); FNLEADFREETHET1GT2GMCTH1: 3_1_N; TOLERANCE: F; COMPONENTNAME: G36010104087_package; MAXGCOUNT: 1; MFSOLDERINGPROP: .; OUMEMAKER: KOA ＫＯＡ; MFPACKAGEMETHOP: S; MFFORMINGDIVP: KC; MOUNTINGFORMSMD: SMD; OUMECLASSIFICATION: 表面実装用固定抵抗器; ASIMVALUE: 100; MFMOUNTSYMBOLP: 80; POWERRATING: 63m; OUMEMAKERKATAMEI: RK73H1JTD1000F; NUMBEROFELEMENT: 0; VAL2: 63mW; CDMASTERCADCELG: DR802R; PCODE: P01042041426; FNCLASSCODEG: P01-08
R64 = R#1: SQ_PART_MODEL: RES_22; FNPARTSNAMEG: CHIP RESISTOR (2012); USEINPARTSLIST: YES; PARTNAME: GDM010000073; PARTCOMMENT: 代表セル<KC0006> がフットプリントに登録されていません。; OriginalSymbolOrigin: (5080,5080); CaptureCellPackProp: R##1; MFSOLDERINGPROP: .; MFPACKAGEMETHOP: S; MFFORMINGDIVP: KC; MOUNTINGFORMSMD: SMD; OUMECLASSIFICATION: 表面実装用固定抵抗器; MFMOUNTSYMBOLP: 80; NUMBEROFELEMENT: 0; CDMASTERCADCELG: KC0006; PCODE: P01B000000XB; FNCLASSCODEG: P01-08; RESISTANCETOLER: F; POWERRATING: 125m; NOMINALRESISTAN: 6.8; MAXGCOUNT: 1; OUMEPOWER: 1/4; COMPONENTNAME: GDM010000073_package; OUMEMAKER: NAE 松下電子部品; OUMERESISTANCE: 30; OUMECHIPSIZE: 3225; OUMECELLMEI: DR903A; OUMEMAKERKATAMEI: ERJ6RQF6R8V; VAL1: 27(F); PA_PHASE: SCH; PA_LOCK: LOCKED; OUMERANKU: L
R65 = R: SQ_PART_MODEL: RES_470; FNPARTSNAMEG: CHIP RESISTOR (1608); USEINPARTSLIST: YES; PARTNAME: GDM010001564; OriginalSymbolOrigin: (5080,5080); FNLEADFREETHET1GT2GMCTH1: 3_1_N; COMPONENTNAME: GDM010001564_package; MAXGCOUNT: 1; MFSOLDERINGPROP: .; OUMEMAKER: NAE 松下電子部品; MFPACKAGEMETHOP: S; MFFORMINGDIVP: KC; MOUNTINGFORMSMD: SMD; OUMECLASSIFICATION: 表面実装用固定抵抗器; RESISTANCETOLER: D; MFMOUNTSYMBOLP: 80; POWERRATING: 63m; OUMEMAKERKATAMEI: ERJ3RBD681V; NOMINALRESISTAN: 680; NUMBEROFELEMENT: 0; VAL2: 63mW; VAL1: 470(F); CDMASTERCADCELG: DR802R; PCODE: P01119023119; FNCLASSCODEG: P01-08
R66 R107 = R: SQ_PART_MODEL: RES_1K; FNPARTSNAMEG: CHIP RESISTOR (1608); USEINPARTSLIST: YES; PARTNAME: GDM010001035; OriginalSymbolOrigin: (5080,5080); FNLEADFREETHET1GT2GMCTH1: 3_1_N; COMPONENTNAME: GDM010001035_package; MAXGCOUNT: 1; MFSOLDERINGPROP: .; OUMEMAKER: NAE 松下電子部品; MFPACKAGEMETHOP: S; MFFORMINGDIVP: KC; MOUNTINGFORMSMD: SMD; OUMECLASSIFICATION: 表面実装用固定抵抗器; RESISTANCETOLER: F; MFMOUNTSYMBOLP: 80; POWERRATING: 63m; OUMEMAKERKATAMEI: ERJ3GEYF102V; NOMINALRESISTAN: 1K; NUMBEROFELEMENT: 0; VAL2: 63mW; CDMASTERCADCELG: DR802R; PCODE: P01042521621; FNCLASSCODEG: P01-08
R67 R72 = R: FNPARTSNAMEG: CHIP RESISTOR (1608); USEINPARTSLIST: YES; PARTNAME: GDM010001021; OriginalSymbolOrigin: (5080,5080); FNLEADFREETHET1GT2GMCTH1: 3_1_N; COMPONENTNAME: GDM010001021_package; MAXGCOUNT: 1; MFSOLDERINGPROP: .; OUMEMAKER: NAE 松下電子部品; MFPACKAGEMETHOP: S; MFFORMINGDIVP: KC; MOUNTINGFORMSMD: SMD; OUMECLASSIFICATION: 表面実装用固定抵抗器; RESISTANCETOLER: F; MFMOUNTSYMBOLP: 80; POWERRATING: 63m; OUMEMAKERKATAMEI: ERJ3GEYF822V; NOMINALRESISTAN: 8.2K; NUMBEROFELEMENT: 0; CDMASTERCADCELG: DR802R; PCODE: P01042507625; FNCLASSCODEG: P01-08
R68 R69 = R: FNPARTSNAMEG: CHIP RESISTOR (1608); USEINPARTSLIST: YES; PARTNAME: GDM010001135; OriginalSymbolOrigin: (5080,5080); FNLEADFREETHET1GT2GMCTH1: 3_1_N; COMPONENTNAME: GDM010001135_package; MAXGCOUNT: 1; MFSOLDERINGPROP: .; OUMEMAKER: NAE 松下電子部品; MFPACKAGEMETHOP: S; MFFORMINGDIVP: KC; MOUNTINGFORMSMD: SMD; OUMECLASSIFICATION: 表面実装用固定抵抗器; RESISTANCETOLER: F; MFMOUNTSYMBOLP: 80; POWERRATING: 63m; OUMEMAKERKATAMEI: ERJ3GEYF471V; NOMINALRESISTAN: 470; NUMBEROFELEMENT: 0; CDMASTERCADCELG: DR802R; PCODE: P01042365621; FNCLASSCODEG: P01-08
R70 R71 = R: SQ_PART_MODEL: RES_1; FNPARTSNAMEG: CHIP RESISTOR (2012); USEINPARTSLIST: YES; PARTNAME: G36010106081; OriginalSymbolOrigin: (5080,5080); COMPONENTNAME: G36010106081_package; MAXGCOUNT: 1; MFSOLDERINGPROP: .; OUMEMAKER: NAE 松下電子部品; MFPACKAGEMETHOP: S; MFFORMINGDIVP: KC; MOUNTINGFORMSMD: SMD; OUMECLASSIFICATION: 表面実装用固定抵抗器; RESISTANCETOLER: F; MFMOUNTSYMBOLP: 90; POWERRATING: 250m; OUMEMAKERKATAMEI: ERJ6RQF1R0V; NUMBEROFELEMENT: 0; VAL2: 125mW; CDMASTERCADCELG: DR910A; PCODE: P01048017210; FNCLASSCODEG: P01-08
R73 = R: SQ_PART_MODEL: RES_10K; FNPARTSNAMEG: CHIP RESISTOR (1608); USEINPARTSLIST: YES; PARTNAME: G36010027249; OriginalSymbolOrigin: (5080,5080); FNLEADFREETHET1GT2GMCTH1: 3_1_N; COMPONENTNAME: GDM010001006_package; MAXGCOUNT: 1; MFSOLDERINGPROP: .; OUMEMAKER: NAE 松下電子部品; MFPACKAGEMETHOP: S; MFFORMINGDIVP: KC; MOUNTINGFORMSMD: SMD; OUMECLASSIFICATION: 表面実装用固定抵抗器; RESISTANCETOLER: F; MFMOUNTSYMBOLP: 80; POWERRATING: 63m; OUMEMAKERKATAMEI: ERJ3GEYF103V; NOMINALRESISTAN: 10K; NUMBEROFELEMENT: 0; VAL2: 63mW; VAL1: 10K(F); CDMASTERCADCELG: DR802R; PCODE: P01042049620; FNCLASSCODEG: P01-08
R74 = R: SQ_PART_MODEL: RES_10K; FNPARTSNAMEG: CHIP RESISTOR (1608); USEINPARTSLIST: YES; PARTNAME: GDM010001006; OriginalSymbolOrigin: (5080,5080); FNLEADFREETHET1GT2GMCTH1: 3_1_N; COMPONENTNAME: GDM010001006_package; MAXGCOUNT: 1; MFSOLDERINGPROP: .; OUMEMAKER: NAE 松下電子部品; MFPACKAGEMETHOP: S; MFFORMINGDIVP: KC; MOUNTINGFORMSMD: SMD; OUMECLASSIFICATION: 表面実装用固定抵抗器; RESISTANCETOLER: F; MFMOUNTSYMBOLP: 80; POWERRATING: 63m; OUMEMAKERKATAMEI: ERJ3GEYF103V; NOMINALRESISTAN: 10K; NUMBEROFELEMENT: 0; VAL2: 63mW; CDMASTERCADCELG: DR802R; PCODE: P01042049620; FNCLASSCODEG: P01-08
R75 = R: SQ_PART_MODEL: RES_10; FNPARTSNAMEG: CHIP RESISTOR (2012); USEINPARTSLIST: YES; PARTNAME: G36010009016; OriginalSymbolOrigin: (5080,5080); FNLEADFREETHET1GT2GMCTH1: 3_1_N; TOLERANCE: F; COMPONENTNAME: G36010009016_package; MAXGCOUNT: 1; MFSOLDERINGPROP: .; OUMEMAKER: HDK 北陸電気工業; MFPACKAGEMETHOP: S; MFFORMINGDIVP: KC; MOUNTINGFORMSMD: SMD; OUMECLASSIFICATION: 表面実装用固定抵抗器; ASIMVALUE: 10; MFMOUNTSYMBOLP: 90; POWERRATING: 100m; OUMEMAKERKATAMEI: CR1/10 100FV; NUMBEROFELEMENT: 0; VAL2: 125mW; CDMASTERCADCELG: DR910A; PCODE: P01043091222; FNCLASSCODEG: P01-08
R76 R77 = R: SQ_PART_MODEL: RES_2.2; FNPARTSNAMEG: CHIP RESISTOR (3216); USEINPARTSLIST: YES; PARTNAME: G36010101093; PARTCOMMENT: 代表セル<KC0014> がフットプリントに登録されていません。; OriginalSymbolOrigin: (5080,5080); COMPONENTNAME: GDM010000344_package; MAXGCOUNT: 1; MFSOLDERINGPROP: .; OUMEMAKER: ROH ロー・; MFPACKAGEMETHOP: S; MFFORMINGDIVP: KC; MOUNTINGFORMSMD: SMD; OUMECLASSIFICATION: 表面実装用固定抵抗器; RESISTANCETOLER: F; MFMOUNTSYMBOLP: 80; POWERRATING: 250m; OUMEMAKERKATAMEI: MCR18EZHFA2R20; NOMINALRESISTAN: 2.2; NUMBEROFELEMENT: 0; CDMASTERCADCELG: KC0014; PCODE: P01B0000018W; FNCLASSCODEG: P01-08
R78 = R: FNPARTSNAMEG: CHIP RESISTOR (1608); USEINPARTSLIST: YES; PARTNAME: GDM010001098; OriginalSymbolOrigin: (5080,5080); FNLEADFREETHET1GT2GMCTH1: 3_1_N; COMPONENTNAME: GDM010001098_package; MAXGCOUNT: 1; MFSOLDERINGPROP: .; OUMEMAKER: NAE 松下電子部品; MFPACKAGEMETHOP: S; MFFORMINGDIVP: KC; MOUNTINGFORMSMD: SMD; OUMECLASSIFICATION: 表面実装用固定抵抗器; RESISTANCETOLER: F; MFMOUNTSYMBOLP: 80; POWERRATING: 63m; OUMEMAKERKATAMEI: ERJ3GEYF122V; NOMINALRESISTAN: 1.2K; NUMBEROFELEMENT: 0; CDMASTERCADCELG: DR802R; PCODE: P01042012624; FNCLASSCODEG: P01-08
R79 = R: SQ_PART_MODEL: RES_47K; FNPARTSNAMEG: CHIP RESISTOR (1608); USEINPARTSLIST: YES; PARTNAME: GDM010001028; OriginalSymbolOrigin: (5080,5080); TOLERANCE: F; ASIMVALUE: 47K; FNLEADFREETHET1GT2GMCTH1: 3_1_N; COMPONENTNAME: G36010027058_package; MAXGCOUNT: 1; MFSOLDERINGPROP: .; OUMEMAKER: ROH ロー・; MFPACKAGEMETHOP: S; MFFORMINGDIVP: KC; MOUNTINGFORMSMD: SMD; OUMECLASSIFICATION: 表面実装用固定抵抗器; MFMOUNTSYMBOLP: 80; POWERRATING: 63m; OUMEMAKERKATAMEI: MCR03EZPFX1502; NOMINALRESISTAN: 15K; NUMBEROFELEMENT: 0; VAL2: 63mW; VAL1: 47K(F); CDMASTERCADCELG: DR802R; PCODE: P01042113727; FNCLASSCODEG: P01-08
R80 = R: SQ_PART_MODEL: RES_120K; FNPARTSNAMEG: CHIP RESISTOR (1608); USEINPARTSLIST: YES; PARTNAME: G36010104438; OriginalSymbolOrigin: (5080,5080); TOLERANCE: F; ASIMVALUE: 120K; MAXGCOUNT: 1; COMPONENTNAME: G36010027010_package; MFSOLDERINGPROP: .; OUMEMAKER: ROH ロー・; MFPACKAGEMETHOP: S; MFFORMINGDIVP: KC; MOUNTINGFORMSMD: SMD; OUMECLASSIFICATION: 表面実装用固定抵抗器; MFMOUNTSYMBOLP: 80; POWERRATING: 63m; OUMEMAKERKATAMEI: MCR03EZPFX4703; NUMBEROFELEMENT: 0; VAL2: 63mW; VAL1: 120K(F); CDMASTERCADCELG: DR802R; PCODE: P01042369728; FNCLASSCODEG: P01-08; FNLEADFREETHET1GT2GMCTH1: 3_1_N; NOMINALRESISTAN: 470K
R81 = R: SQ_PART_MODEL: RES_150K; FNPARTSNAMEG: CHIP RESISTOR (1608); USEINPARTSLIST: YES; PARTNAME: G36010104438; OriginalSymbolOrigin: (5080,5080); TOLERANCE: F; ASIMVALUE: 150K; NOTMOUNT: MOUNT; MAXGCOUNT: 1; COMPONENTNAME: G36010027126_package; MFSOLDERINGPROP: .; OUMEMAKER: HDK 北陸電気工業; MFPACKAGEMETHOP: S; MFFORMINGDIVP: KC; MOUNTINGFORMSMD: SMD; OUMECLASSIFICATION: 表面実装用固定抵抗器; MFMOUNTSYMBOLP: 80; POWERRATING: 63m; OUMEMAKERKATAMEI: CR1/16 683FV; NUMBEROFELEMENT: 0; VAL2: 63mW; VAL1: 150K(F); CDMASTERCADCELG: DR802R; PCODE: P01042456220; FNCLASSCODEG: P01-08; FNLEADFREETHET1GT2GMCTH1: 3_1_N; NOMINALRESISTAN: 68K
R82 = R: SQ_PART_MODEL: RES_1K; FNPARTSNAMEG: CHIP RESISTOR (1608); USEINPARTSLIST: YES; PARTNAME: GDM010001098; OriginalSymbolOrigin: (5080,5080); TOLERANCE: F; ASIMVALUE: 1K; FNLEADFREETHET1GT2GMCTH1: 3_1_N; COMPONENTNAME: G36010027324_package; MAXGCOUNT: 1; MFSOLDERINGPROP: .; OUMEMAKER: HDK 北陸電気工業; MFPACKAGEMETHOP: S; MFFORMINGDIVP: KC; MOUNTINGFORMSMD: SMD; OUMECLASSIFICATION: 表面実装用固定抵抗器; MFMOUNTSYMBOLP: 80; POWERRATING: 63m; OUMEMAKERKATAMEI: CR1/16 102FV; NUMBEROFELEMENT: 0; VAL2: 63mW; CDMASTERCADCELG: DR802R; PCODE: P01042521225; FNCLASSCODEG: P01-08
R83 R84 R89 R90 = R: SQ_PART_MODEL: RES_10K; FNPARTSNAMEG: CHIP RESISTOR (1608); USEINPARTSLIST: YES; PARTNAME: G36010027034; OriginalSymbolOrigin: (5080,5080); FNLEADFREETHET1GT2GMCTH1: 3_1_N; TOLERANCE: F; COMPONENTNAME: G36010027034_package; MAXGCOUNT: 1; MFSOLDERINGPROP: .; OUMEMAKER: SAM 三星電機; MFPACKAGEMETHOP: S; MFFORMINGDIVP: KC; MOUNTINGFORMSMD: SMD; OUMECLASSIFICATION: 表面実装用固定抵抗器; ASIMVALUE: 10K; MFMOUNTSYMBOLP: 80; POWERRATING: 63m; OUMEMAKERKATAMEI: RC1608F103CS; NUMBEROFELEMENT: 0; VAL2: 63mW; CDMASTERCADCELG: DR802R; PCODE: P01042049A26; FNCLASSCODEG: P01-08
R85 = R: SQ_PART_MODEL: RES_33K; FNPARTSNAMEG: CHIP RESISTOR (1608); USEINPARTSLIST: YES; PARTNAME: G36010027249; OriginalSymbolOrigin: (5080,5080); TOLERANCE: F; ASIMVALUE: 33K; FNLEADFREETHET1GT2GMCTH1: 3_1_N; COMPONENTNAME: G36010027133_package; MAXGCOUNT: 1; MFSOLDERINGPROP: .; OUMEMAKER: HDK 北陸電気工業; MFPACKAGEMETHOP: S; MFFORMINGDIVP: KC; MOUNTINGFORMSMD: SMD; OUMECLASSIFICATION: 表面実装用固定抵抗器; MFMOUNTSYMBOLP: 80; POWERRATING: 63m; OUMEMAKERKATAMEI: CR1/16 104FV; NOMINALRESISTAN: 100K; NUMBEROFELEMENT: 0; VAL2: 63mW; VAL1: 33K(F); CDMASTERCADCELG: DR802R; PCODE: P01042045226; FNCLASSCODEG: P01-08
R86 R88 = R: SQ_PART_MODEL: RES_22K; FNPARTSNAMEG: CHIP RESISTOR (1608); USEINPARTSLIST: YES; PARTNAME: G36010027089; OriginalSymbolOrigin: (5080,5080); TOLERANCE: F; ASIMVALUE: 22K; FNLEADFREETHET1GT2GMCTH1: 3_1_N; COMPONENTNAME: G36010027089_package; MAXGCOUNT: 1; MFSOLDERINGPROP: .; OUMEMAKER: KOA ＫＯＡ; MFPACKAGEMETHOP: S; MFFORMINGDIVP: KC; MOUNTINGFORMSMD: SMD; OUMECLASSIFICATION: 表面実装用固定抵抗器; MFMOUNTSYMBOLP: 80; POWERRATING: 63m; OUMEMAKERKATAMEI: RK73H1JTD2202F; NUMBEROFELEMENT: 0; VAL2: 63mW; CDMASTERCADCELG: DR802R; PCODE: P01042207426; FNCLASSCODEG: P01-08
R87 = R: SQ_PART_MODEL: RES_4.7K; FNPARTSNAMEG: CHIP RESISTOR (1608); USEINPARTSLIST: YES; PARTNAME: G36010027249; OriginalSymbolOrigin: (5080,5080); TOLERANCE: F; ASIMVALUE: 4.7K; FNLEADFREETHET1GT2GMCTH1: 3_1_N; COMPONENTNAME: G36010027249_package; MAXGCOUNT: 1; MFSOLDERINGPROP: .; OUMEMAKER: ROH ロー・; MFPACKAGEMETHOP: S; MFFORMINGDIVP: KC; MOUNTINGFORMSMD: SMD; OUMECLASSIFICATION: 表面実装用固定抵抗器; MFMOUNTSYMBOLP: 80; POWERRATING: 63m; OUMEMAKERKATAMEI: MCR03EZPFX4701; NUMBEROFELEMENT: 0; VAL2: 63mW; CDMASTERCADCELG: DR802R; PCODE: P01042513725; FNCLASSCODEG: P01-08
R91 R93 R95 R97 = R: SQ_PART_MODEL: RES_0; FNPARTSNAMEG: CHIP RESISTOR (3216); USEINPARTSLIST: YES; PARTNAME: G36010101093; OriginalSymbolOrigin: (5080,5080); COMPONENTNAME: G36010101093_package; MAXGCOUNT: 1; MFSOLDERINGPROP: .; OUMEMAKER: NAE 松下電子部品; MFPACKAGEMETHOP: S; MFFORMINGDIVP: KC; MOUNTINGFORMSMD: SMD; OUMECLASSIFICATION: 表面実装用固定抵抗器; RESISTANCETOLER: F; MFMOUNTSYMBOLP: 90; POWERRATING: 250m; OUMEMAKERKATAMEI: ERJ8RQF4R7V; NOMINALRESISTAN: 4.7; NUMBEROFELEMENT: 0; VAL1: 0(X); CDMASTERCADCELG: DR901A; PCODE: P01127006111; FNCLASSCODEG: P01-08
R92 R94 R96 R98 = R: SQ_PART_MODEL: RES_4.7; FNPARTSNAMEG: CHIP RESISTOR (3216); USEINPARTSLIST: YES; PARTNAME: G36010101093; OriginalSymbolOrigin: (5080,5080); COMPONENTNAME: G36010101093_package; MAXGCOUNT: 1; MFSOLDERINGPROP: .; OUMEMAKER: NAE 松下電子部品; MFPACKAGEMETHOP: S; MFFORMINGDIVP: KC; MOUNTINGFORMSMD: SMD; OUMECLASSIFICATION: 表面実装用固定抵抗器; RESISTANCETOLER: F; MFMOUNTSYMBOLP: 90; POWERRATING: 250m; OUMEMAKERKATAMEI: ERJ8RQF4R7V; NOMINALRESISTAN: 4.7; NUMBEROFELEMENT: 0; CDMASTERCADCELG: DR901A; PCODE: P01127006111; FNCLASSCODEG: P01-08
R99 R102 R104 = R: SQ_PART_MODEL: RES_6.8K; FNPARTSNAMEG: CHIP RESISTOR (1608); USEINPARTSLIST: YES; PARTNAME: GDM010001027; OriginalSymbolOrigin: (5080,5080); FNLEADFREETHET1GT2GMCTH1: 3_1_N; COMPONENTNAME: G5101105R107_package; MAXGCOUNT: 1; MFSOLDERINGPROP: .; OUMEMAKER: NAE 松下電子部品; MFPACKAGEMETHOP: S; MFFORMINGDIVP: KC; MOUNTINGFORMSMD: SMD; OUMECLASSIFICATION: 表面実装用固定抵抗器; RESISTANCETOLER: F; MFMOUNTSYMBOLP: 80; POWERRATING: 63m; OUMEMAKERKATAMEI: ERJ3GEYF682V; NOMINALRESISTAN: 6.8K; NUMBEROFELEMENT: 0; VAL2: 63mW; CDMASTERCADCELG: DR802R; PCODE: P01042424625; FNCLASSCODEG: P01-08
R100 = R: SQ_PART_MODEL: RES_6.8K; FNPARTSNAMEG: CHIP RESISTOR (1608); USEINPARTSLIST: YES; PARTNAME: GDM010001005; OriginalSymbolOrigin: (5080,5080); FNLEADFREETHET1GT2GMCTH1: 3_1_N; COMPONENTNAME: G5101105R107_package; MAXGCOUNT: 1; MFSOLDERINGPROP: .; OUMEMAKER: NAE 松下電子部品; MFPACKAGEMETHOP: S; MFFORMINGDIVP: KC; MOUNTINGFORMSMD: SMD; OUMECLASSIFICATION: 表面実装用固定抵抗器; RESISTANCETOLER: F; MFMOUNTSYMBOLP: 80; POWERRATING: 63m; OUMEMAKERKATAMEI: ERJ3GEYF682V; NOMINALRESISTAN: 6.8K; NUMBEROFELEMENT: 0; VAL2: 63mW; CDMASTERCADCELG: DR802R; PCODE: P01042424625; FNCLASSCODEG: P01-08
R101 R103 = R: SQ_PART_MODEL: RES_6.8K; FNPARTSNAMEG: CHIP RESISTOR (1608); USEINPARTSLIST: YES; PARTNAME: G36010027188; OriginalSymbolOrigin: (5080,5080); FNLEADFREETHET1GT2GMCTH1: 3_1_N; COMPONENTNAME: G5101105R107_package; MAXGCOUNT: 1; MFSOLDERINGPROP: .; OUMEMAKER: NAE 松下電子部品; MFPACKAGEMETHOP: S; MFFORMINGDIVP: KC; MOUNTINGFORMSMD: SMD; OUMECLASSIFICATION: 表面実装用固定抵抗器; RESISTANCETOLER: F; MFMOUNTSYMBOLP: 80; POWERRATING: 63m; OUMEMAKERKATAMEI: ERJ3GEYF682V; NOMINALRESISTAN: 6.8K; NUMBEROFELEMENT: 0; VAL2: 63mW; CDMASTERCADCELG: DR802R; PCODE: P01042424625; FNCLASSCODEG: P01-08
R105 = R: FNPARTSNAMEG: CHIP RESISTOR (1608); USEINPARTSLIST: YES; PARTNAME: GDM010001035; OriginalSymbolOrigin: (5080,5080); TOLERANCE: F; FNLEADFREETHET1GT2GMCTH1: 3_1_N; COMPONENTNAME: G36010104223_package; MAXGCOUNT: 1; MFSOLDERINGPROP: .; OUMEMAKER: KOA ＫＯＡ; MFPACKAGEMETHOP: S; MFFORMINGDIVP: KC; MOUNTINGFORMSMD: SMD; OUMECLASSIFICATION: 表面実装用固定抵抗器; MFMOUNTSYMBOLP: 80; POWERRATING: 63m; OUMEMAKERKATAMEI: RK73H1JTD3303F; NOMINALRESISTAN: 330K; NUMBEROFELEMENT: 0; CDMASTERCADCELG: DR802R; PCODE: P01042291425; FNCLASSCODEG: P01-08
R106 = R: SQ_PART_MODEL: RES_680K; FNPARTSNAMEG: CHIP RESISTOR (1608); USEINPARTSLIST: YES; PARTNAME: GDM010001035; OriginalSymbolOrigin: (5080,5080); TOLERANCE: F; ASIMVALUE: 680K; FNLEADFREETHET1GT2GMCTH1: 3_1_N; COMPONENTNAME: G36010104223_package; MAXGCOUNT: 1; MFSOLDERINGPROP: .; OUMEMAKER: KOA ＫＯＡ; MFPACKAGEMETHOP: S; MFFORMINGDIVP: KC; MOUNTINGFORMSMD: SMD; OUMECLASSIFICATION: 表面実装用固定抵抗器; MFMOUNTSYMBOLP: 80; POWERRATING: 63m; OUMEMAKERKATAMEI: RK73H1JTD3303F; NOMINALRESISTAN: 330K; NUMBEROFELEMENT: 0; VAL2: 63mW; VAL1: 680K(F); CDMASTERCADCELG: DR802R; PCODE: P01042291425; FNCLASSCODEG: P01-08
R108 = R: SQ_PART_MODEL: RES_100K; FNPARTSNAMEG: CHIP RESISTOR (1608); USEINPARTSLIST: YES; PARTNAME: G36010027133; OriginalSymbolOrigin: (5080,5080); TOLERANCE: F; ASIMVALUE: 100K; FNLEADFREETHET1GT2GMCTH1: 3_1_N; COMPONENTNAME: G36010027133_package; MAXGCOUNT: 1; MFSOLDERINGPROP: .; OUMEMAKER: HDK 北陸電気工業; MFPACKAGEMETHOP: S; MFFORMINGDIVP: KC; MOUNTINGFORMSMD: SMD; OUMECLASSIFICATION: 表面実装用固定抵抗器; MFMOUNTSYMBOLP: 80; POWERRATING: 63m; OUMEMAKERKATAMEI: CR1/16 104FV; NUMBEROFELEMENT: 0; VAL2: 63mW; CDMASTERCADCELG: DR802R; PCODE: P01042045226; FNCLASSCODEG: P01-08
R109 = R: SQ_PART_MODEL: RES_47K; FNPARTSNAMEG: CHIP RESISTOR (1608); USEINPARTSLIST: YES; PARTNAME: G36010027102; OriginalSymbolOrigin: (5080,5080); TOLERANCE: F; ASIMVALUE: 47K; FNLEADFREETHET1GT2GMCTH1: 3_1_N; COMPONENTNAME: G36010027102_package; MAXGCOUNT: 1; MFSOLDERINGPROP: .; OUMEMAKER: KOA ＫＯＡ; MFPACKAGEMETHOP: S; MFFORMINGDIVP: KC; MOUNTINGFORMSMD: SMD; OUMECLASSIFICATION: 表面実装用固定抵抗器; MFMOUNTSYMBOLP: 80; POWERRATING: 63m; OUMEMAKERKATAMEI: RK73H1JTD4702F; NUMBEROFELEMENT: 0; VAL2: 63mW; CDMASTERCADCELG: DR802R; PCODE: P01042373428; FNCLASSCODEG: P01-08
R110 = R: SQ_PART_MODEL: RES_220K; FNPARTSNAMEG: CHIP RESISTOR (1608); USEINPARTSLIST: YES; PARTNAME: G36010011064; OriginalSymbolOrigin: (5080,5080); TOLERANCE: J; ASIMVALUE: 220K; FNLEADFREETHET1GT2GMCTH1: 3_1_N; COMPONENTNAME: G36010011064_package; MAXGCOUNT: 1; MFSOLDERINGPROP: .; OUMEMAKER: KAM 釜屋電機; MFPACKAGEMETHOP: S; MFFORMINGDIVP: KC; MOUNTINGFORMSMD: SMD; OUMECLASSIFICATION: 表面実装用固定抵抗器; MFMOUNTSYMBOLP: 80; POWERRATING: 63m; OUMEMAKERKATAMEI: RMC1/16-105JTP; NOMINALRESISTAN: 1M; NUMBEROFELEMENT: 0; VAL2: 63mW; VAL1: 220K(F); CDMASTERCADCELG: DR802R; PCODE: P01042155321; FNCLASSCODEG: P01-08
R111 = R: SQ_PART_MODEL: RES_220K; FNPARTSNAMEG: CHIP RESISTOR (1608); USEINPARTSLIST: YES; PARTNAME: G36010103097; OriginalSymbolOrigin: (5080,5080); TOLERANCE: J; ASIMVALUE: 220K; MAXGCOUNT: 1; COMPONENTNAME: G36010103097_package; MFSOLDERINGPROP: .; OUMEMAKER: HDK 北陸電気工業; MFPACKAGEMETHOP: S; MFFORMINGDIVP: KC; MOUNTINGFORMSMD: SMD; OUMECLASSIFICATION: 表面実装用固定抵抗器; MFMOUNTSYMBOLP: 80; POWERRATING: 63m; OUMEMAKERKATAMEI: CR1/16 224JV; NUMBEROFELEMENT: 0; VAL2: 63mW; VAL1: 220K(F); CDMASTERCADCELG: DR802R; PCODE: P01042204227; FNCLASSCODEG: P01-08; FNLEADFREETHET1GT2GMCTH1: 3_1_N
R112 = R: SQ_PART_MODEL: RES_2.4K; FNPARTSNAMEG: CHIP RESISTOR (1608); USEINPARTSLIST: YES; PARTNAME: G36010104094; OriginalSymbolOrigin: (5080,5080); MAXGCOUNT: 1; TOLERANCE: F; COMPONENTNAME: G36010104094_package; MFSOLDERINGPROP: .; OUMEMAKER: KAM 釜屋電機; MFPACKAGEMETHOP: S; MFFORMINGDIVP: KC; MOUNTINGFORMSMD: SMD; OUMECLASSIFICATION: 表面実装用固定抵抗器; ASIMVALUE: 2.4K; MFMOUNTSYMBOLP: 80; POWERRATING: 63m; OUMEMAKERKATAMEI: RMC1/16-242FTP; NUMBEROFELEMENT: 0; VAL2: 63mW; CDMASTERCADCELG: DR802R; PCODE: P01042166327; FNCLASSCODEG: P01-08; FNLEADFREETHET1GT2GMCTH1: 3_1_N
R113-R116 R122 = R: SQ_PART_MODEL: RES_10K; FNPARTSNAMEG: CHIP RESISTOR (1608); USEINPARTSLIST: YES; PARTNAME: G36010027034; OriginalSymbolOrigin: (5080,5080); TOLERANCE: F; COMPONENTNAME: G36010027034_package; MAXGCOUNT: 1; MFSOLDERINGPROP: .; OUMEMAKER: SAM 三星電機; MFPACKAGEMETHOP: S; MFFORMINGDIVP: KC; MOUNTINGFORMSMD: SMD; OUMECLASSIFICATION: 表面実装用固定抵抗器; ASIMVALUE: 10K; MFMOUNTSYMBOLP: 80; POWERRATING: 63m; OUMEMAKERKATAMEI: RC1608F103CS; NUMBEROFELEMENT: 0; VAL2: 63mW; CDMASTERCADCELG: DR802R; PCODE: P01042049A26; FNCLASSCODEG: P01-08
R117 R118 = R: SQ_PART_MODEL: RES_3.3K; FNPARTSNAMEG: CHIP RESISTOR (1608); USEINPARTSLIST: YES; PARTNAME: G36010027027; OriginalSymbolOrigin: (5080,5080); TOLERANCE: F; ASIMVALUE: 3.3K; COMPONENTNAME: G36010027027_package; MAXGCOUNT: 1; MFSOLDERINGPROP: .; OUMEMAKER: ROH ロー・; MFPACKAGEMETHOP: S; MFFORMINGDIVP: KC; MOUNTINGFORMSMD: SMD; OUMECLASSIFICATION: 表面実装用固定抵抗器; MFMOUNTSYMBOLP: 80; POWERRATING: 63m; OUMEMAKERKATAMEI: MCR03EZPFX3301; NUMBEROFELEMENT: 0; VAL2: 63mW; CDMASTERCADCELG: DR802R; PCODE: P01042250729; FNCLASSCODEG: P01-08
R119 R127 = R: SQ_PART_MODEL: RES_1K; FNPARTSNAMEG: CHIP RESISTOR (1608); USEINPARTSLIST: YES; PARTNAME: G36010027324; OriginalSymbolOrigin: (5080,5080); TOLERANCE: F; COMPONENTNAME: G36010027324_package; MAXGCOUNT: 1; MFSOLDERINGPROP: .; OUMEMAKER: HDK 北陸電気工業; MFPACKAGEMETHOP: S; MFFORMINGDIVP: KC; MOUNTINGFORMSMD: SMD; OUMECLASSIFICATION: 表面実装用固定抵抗器; ASIMVALUE: 1K; MFMOUNTSYMBOLP: 80; POWERRATING: 63m; OUMEMAKERKATAMEI: CR1/16 102FV; NUMBEROFELEMENT: 0; VAL2: 63mW; CDMASTERCADCELG: DR802R; PCODE: P01042521225; FNCLASSCODEG: P01-08
R120 = R: SQ_PART_MODEL: RES_1K; FNPARTSNAMEG: CHIP RESISTOR (1608); USEINPARTSLIST: YES; PARTNAME: G36010027324; OriginalSymbolOrigin: (5080,5080); ASIMVALUE: 1K; NOTMOUNT: MOUNT; FNLEADFREETHET1GT2GMCTH1: 3_1_N; COMPONENTNAME: G5101105R107_package; MAXGCOUNT: 1; MFSOLDERINGPROP: .; OUMEMAKER: NAE 松下電子部品; MFPACKAGEMETHOP: S; MFFORMINGDIVP: KC; MOUNTINGFORMSMD: SMD; OUMECLASSIFICATION: 表面実装用固定抵抗器; RESISTANCETOLER: F; MFMOUNTSYMBOLP: 80; POWERRATING: 63m; OUMEMAKERKATAMEI: ERJ3GEYF682V; NOMINALRESISTAN: 6.8K; NUMBEROFELEMENT: 0; VAL2: 63mW; VAL1: 1K(F); CDMASTERCADCELG: DR802R; PCODE: P01042424625; FNCLASSCODEG: P01-08
R121 = R: FNPARTSNAMEG: CHIP RESISTOR (1608); USEINPARTSLIST: YES; PARTNAME: G36010027171; OriginalSymbolOrigin: (5080,5080); FNLEADFREETHET1GT2GMCTH1: 3_1_N; TOLERANCE: F; COMPONENTNAME: G36010027171_package; MAXGCOUNT: 1; MFSOLDERINGPROP: .; OUMEMAKER: NAE 松下電子部品; MFPACKAGEMETHOP: S; MFFORMINGDIVP: KC; MOUNTINGFORMSMD: SMD; OUMECLASSIFICATION: 表面実装用固定抵抗器; MFMOUNTSYMBOLP: 80; POWERRATING: 63m; OUMEMAKERKATAMEI: ERJ3GEYF333V; NOMINALRESISTAN: 33K; NUMBEROFELEMENT: 0; CDMASTERCADCELG: DR802R; PCODE: P01042295621; FNCLASSCODEG: P01-08
R123 = R: SQ_PART_MODEL: RES_82K; FNPARTSNAMEG: CHIP RESISTOR (2012); USEINPARTSLIST: YES; PARTNAME: 5P9L1083P100; OriginalSymbolOrigin: (5080,5080); TOLERANCE: F; ASIMVALUE: 82K; NOTMOUNT: MOUNT; FNLEADFREETHET1GT2GMCTH1: 3_1_N; COMPONENTNAME: G36010009054_package; MAXGCOUNT: 1; MFSOLDERINGPROP: .; OUMEMAKER: HDK 北陸電気工業; MFPACKAGEMETHOP: S; MFFORMINGDIVP: KC; MOUNTINGFORMSMD: SMD; OUMECLASSIFICATION: 表面実装用固定抵抗器; MFMOUNTSYMBOLP: 90; POWERRATING: 100m; OUMEMAKERKATAMEI: CR1/10 104FV; NOMINALRESISTAN: 100K; NUMBEROFELEMENT: 0; VAL2: 125mW; VAL1: 82K(F); CDMASTERCADCELG: DR910A; PCODE: P01043109224; FNCLASSCODEG: P01-08
R124 = R: SQ_PART_MODEL: RES_33K; FNPARTSNAMEG: CHIP RESISTOR (2012); USEINPARTSLIST: YES; PARTNAME: 5P9L1083P100; OriginalSymbolOrigin: (5080,5080); TOLERANCE: F; ASIMVALUE: 33K; NOTMOUNT: MOUNT; FNLEADFREETHET1GT2GMCTH1: 3_1_N; COMPONENTNAME: G36010009160_package; MAXGCOUNT: 1; MFSOLDERINGPROP: .; OUMEMAKER: KOA ＫＯＡ; MFPACKAGEMETHOP: S; MFFORMINGDIVP: KC; MOUNTINGFORMSMD: SMD; OUMECLASSIFICATION: 表面実装用固定抵抗器; MFMOUNTSYMBOLP: 90; POWERRATING: 100m; OUMEMAKERKATAMEI: RK73H2ATD1502F; NOMINALRESISTAN: 15K; NUMBEROFELEMENT: 0; VAL2: 125mW; VAL1: 33K(F); CDMASTERCADCELG: DR910A; PCODE: P01043278524; FNCLASSCODEG: P01-08
R125 = R: SQ_PART_MODEL: RES_22K; FNPARTSNAMEG: CHIP RESISTOR (2012); USEINPARTSLIST: YES; PARTNAME: 5P9L1083P100; OriginalSymbolOrigin: (5080,5080); TOLERANCE: F; ASIMVALUE: 22K; NOTMOUNT: MOUNT; FNLEADFREETHET1GT2GMCTH1: 3_1_N; COMPONENTNAME: G36010009474_package; MAXGCOUNT: 1; MFSOLDERINGPROP: .; OUMEMAKER: KOA ＫＯＡ; MFPACKAGEMETHOP: S; MFFORMINGDIVP: KC; MOUNTINGFORMSMD: SMD; OUMECLASSIFICATION: 表面実装用固定抵抗器; MFMOUNTSYMBOLP: 90; POWERRATING: 100m; OUMEMAKERKATAMEI: RK73H2ATD3302F; NOMINALRESISTAN: 33K; NUMBEROFELEMENT: 0; VAL2: 125mW; VAL1: 22K(F); CDMASTERCADCELG: DR910A; PCODE: P01043665522; FNCLASSCODEG: P01-08
R126 = R: SQ_PART_MODEL: RES_2.2K; FNPARTSNAMEG: CHIP RESISTOR (1608); USEINPARTSLIST: YES; PARTNAME: G36010104339; OriginalSymbolOrigin: (5080,5080); FNLEADFREETHET1GT2GMCTH1: 3_1_N; COMPONENTNAME: G36010104339_package; MAXGCOUNT: 1; MFSOLDERINGPROP: .; OUMEMAKER: KOA ＫＯＡ; MFPACKAGEMETHOP: S; MFFORMINGDIVP: KC; MOUNTINGFORMSMD: SMD; OUMECLASSIFICATION: 表面実装用固定抵抗器; RESISTANCETOLER: F; MFMOUNTSYMBOLP: 80; POWERRATING: 63m; OUMEMAKERKATAMEI: RK73H1JTD2201F; NOMINALRESISTAN: 2.2K; NUMBEROFELEMENT: 0; VAL2: 63mW; CDMASTERCADCELG: DR802R; PCODE: P01042159428; FNCLASSCODEG: P01-08
R128 = R: FNPARTSNAMEG: CHIP RESISTOR (1608); USEINPARTSLIST: YES; PARTNAME: G36010104063; OriginalSymbolOrigin: (5080,5080); FNLEADFREETHET1GT2GMCTH1: 3_1_N; TOLERANCE: F; COMPONENTNAME: G36010104063_package; MAXGCOUNT: 1; MFSOLDERINGPROP: .; OUMEMAKER: NAE 松下電子部品; MFPACKAGEMETHOP: S; MFFORMINGDIVP: KC; MOUNTINGFORMSMD: SMD; OUMECLASSIFICATION: 表面実装用固定抵抗器; MFMOUNTSYMBOLP: 80; POWERRATING: 63m; OUMEMAKERKATAMEI: ERJ3GEYF100V; NOMINALRESISTAN: 10; NUMBEROFELEMENT: 0; CDMASTERCADCELG: DR802R; PCODE: P01042036620; FNCLASSCODEG: P01-08
R129 R130 = R#1: SQ_PART_MODEL: RES_15K; FNPARTSNAMEG: CHIP RESISTOR (3216); USEINPARTSLIST: YES; PARTNAME: G36010101093; OriginalSymbolOrigin: (5080,5080); CaptureCellPackProp: R##1; COMPONENTNAME: G36010101093_package; MAXGCOUNT: 1; MFSOLDERINGPROP: .; OUMEMAKER: NAE 松下電子部品; MFPACKAGEMETHOP: S; MFFORMINGDIVP: KC; MOUNTINGFORMSMD: SMD; OUMECLASSIFICATION: 表面実装用固定抵抗器; RESISTANCETOLER: F; MFMOUNTSYMBOLP: 90; POWERRATING: 250m; OUMEMAKERKATAMEI: ERJ8RQF4R7V; NOMINALRESISTAN: 4.7; NUMBEROFELEMENT: 0; VAL1: 15K(F); CDMASTERCADCELG: DR901A; PCODE: P01127006111; FNCLASSCODEG: P01-08
R131 = R: SQ_PART_MODEL: RES_2.2K; FNPARTSNAMEG: CHIP RESISTOR (1608); USEINPARTSLIST: YES; PARTNAME: G36010104339; OriginalSymbolOrigin: (5080,5080); COMPONENTNAME: G36010104339_package; MAXGCOUNT: 1; MFSOLDERINGPROP: .; OUMEMAKER: KOA ＫＯＡ; MFPACKAGEMETHOP: S; MFFORMINGDIVP: KC; MOUNTINGFORMSMD: SMD; OUMECLASSIFICATION: 表面実装用固定抵抗器; RESISTANCETOLER: F; MFMOUNTSYMBOLP: 80; POWERRATING: 63m; OUMEMAKERKATAMEI: RK73H1JTD2201F; NOMINALRESISTAN: 2.2K; NUMBEROFELEMENT: 0; VAL2: 63mW; CDMASTERCADCELG: DR802R; PCODE: P01042159428; FNCLASSCODEG: P01-08
R132 = R#1: SQ_PART_MODEL: RES_56K; FNPARTSNAMEG: CHIP RESISTOR (3216); USEINPARTSLIST: YES; PARTNAME: G36010101093; OriginalSymbolOrigin: (5080,5080); CaptureCellPackProp: R##1; COMPONENTNAME: G36010101093_package; MAXGCOUNT: 1; MFSOLDERINGPROP: .; OUMEMAKER: NAE 松下電子部品; MFPACKAGEMETHOP: S; MFFORMINGDIVP: KC; MOUNTINGFORMSMD: SMD; OUMECLASSIFICATION: 表面実装用固定抵抗器; RESISTANCETOLER: F; MFMOUNTSYMBOLP: 90; POWERRATING: 250m; OUMEMAKERKATAMEI: ERJ8RQF4R7V; NOMINALRESISTAN: 4.7; NUMBEROFELEMENT: 0; VAL1: 56K(F); CDMASTERCADCELG: DR901A; PCODE: P01127006111; FNCLASSCODEG: P01-08
R162 R163 = R#1: SQ_PART_MODEL: RES_4.7K; FNPARTSNAMEG: CHIP RESISTOR (6432); USEINPARTSLIST: YES; PARTNAME: G36010036012; OriginalSymbolOrigin: (5080,5080); CaptureCellPackProp: R##1; TOLERANCE: J; ASIMVALUE: 4.7K; COMPONENTNAME: G36010036012_package; MAXGCOUNT: 1; MFSOLDERINGPROP: .; OUMEMAKER: KAM 釜屋電機; MFPACKAGEMETHOP: S; MFFORMINGDIVP: KC; MOUNTINGFORMSMD: SMD; OUMECLASSIFICATION: 表面実装用固定抵抗器; MFMOUNTSYMBOLP: 80; OUMEMAKERKATAMEI: RMC1-6R8JTE; NOMINALRESISTAN: 6.8; NUMBEROFELEMENT: 0; VAL1: 4.7K(F); CDMASTERCADCELG: R8100A; PCODE: P01062003213; FNCLASSCODEG: P01-08
U?#2 = WAKU_DEF100: PLOTTIME: HH:MM; SAVEAREA0: 218350,-40131,416688,63935; TIME: 14:30:25; UPDATEUSER: t5459927; UPDATETIME: 13:20:45; SAVECOUNT: 5; OriginalSymbolOrigin: (10160,284480)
